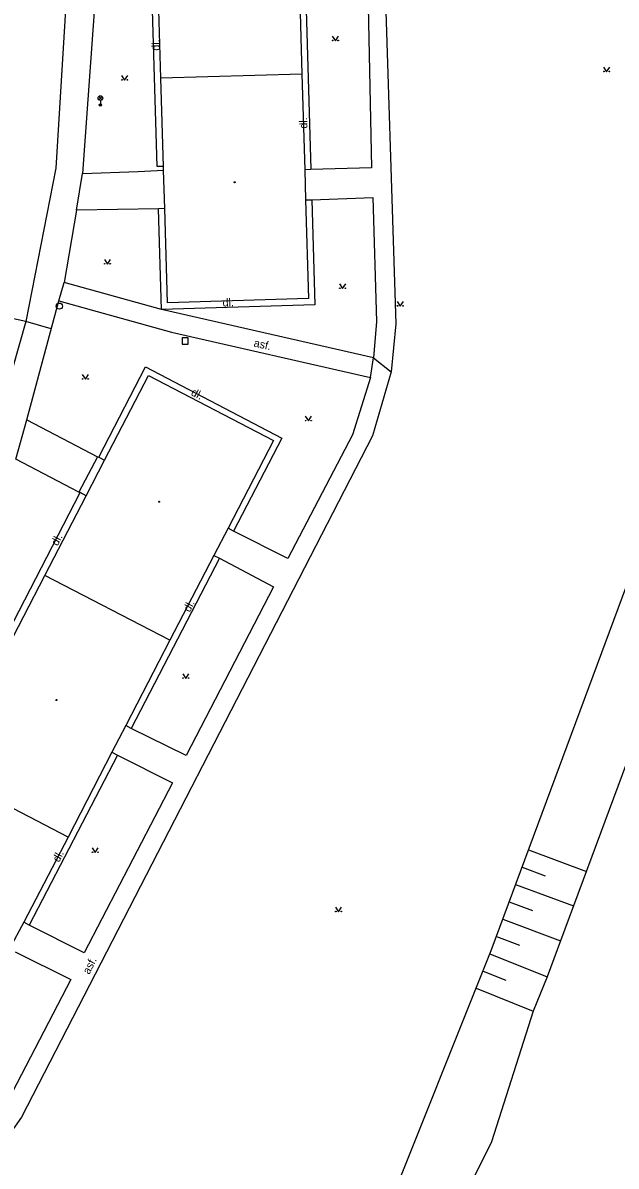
# Model space of a CAD drawing. Extents: x -602419 to -601554, y -1162937 to -1162362.
# Drawn here: x -601746.3 to -601698.2, y -1162548.7 to -1162455.9 of the extents above; entities that cross this region are included whole.
import ezdxf

# ---------------------------------------------------------------- set-up
doc = ezdxf.new("R2010")
doc.units = 0
doc.layers.add('Podklad', color=7, linetype='Continuous')

msp = doc.modelspace()

# ---------------------------------------------------------------- linework, layer by layer
at = {"layer": 'Podklad'}
for p, q in [((-601740.1625, -1162462.13), (-601739.8975, -1162461.865)), ((-601740.1625, -1162461.865), (-601739.8975, -1162462.13)), ((-601740.03, -1162462.185), (-601740.03, -1162462.56))]:
    msp.add_line(p, q, dxfattribs=at)
for points in [[(-601718.62, -1162386.7199), (-601719.1599, -1162386.65), (-601718.15, -1162413.82), (-601705.36, -1162413.11), (-601705.25, -1162448.94), (-601717.05, -1162449.02), (-601716.04, -1162480.32), (-601716.4099, -1162484.2199), (-601717.94, -1162489.4099), (-601746.45, -1162544.74), (-601749.56, -1162549.13)], [(-601734.59, -1162580.77), (-601717.04, -1162553.06), (-601708.29, -1162531.19), (-601693.48, -1162491.34), (-601681.9183, -1162447.6661), (-601678.2, -1162433.62)], [(-601742.71, -1162452.15), (-601743.65, -1162467.7)], [(-601723.89, -1162452.06), (-601723.6599, -1162460.06)], [(-601723.39, -1162452.04), (-601722.94, -1162467.8)], [(-601718.35, -1162451.9), (-601718.01, -1162467.6599)], [(-601735.84, -1162453.01), (-601740.4, -1162453.07), (-601741.48, -1162468.11), (-601736.96, -1162467.96), (-601734.9, -1162467.85)], [(-601735.4099, -1162467.56), (-601735.84, -1162453.01)], [(-601735.12, -1162460.39), (-601735.33, -1162452.99)], [(-601721.2, -1162456.975), (-601720.95, -1162457.35), (-601720.7, -1162456.975)], [(-601699.17, -1162459.485), (-601698.92, -1162459.86), (-601698.67, -1162459.485)], [(-601738.31, -1162460.165), (-601738.06, -1162460.54), (-601737.81, -1162460.165)], [(-601723.6599, -1162460.06), (-601735.12, -1162460.39)], [(-601734.9099, -1162467.55), (-601735.12, -1162460.39)], [(-601723.6599, -1162460.06), (-601723.44, -1162467.81)], [(-601743.65, -1162467.7), (-601746.09, -1162480.13)], [(-601741.98, -1162471.09), (-601741.48, -1162468.11)], [(-601734.9099, -1162467.55), (-601735.4099, -1162467.56)], [(-601734.9, -1162467.85), (-601734.9099, -1162467.55)], [(-601734.81, -1162470.9699), (-601734.9, -1162467.85)], [(-601722.94, -1162467.8), (-601723.44, -1162467.81)], [(-601723.44, -1162467.81), (-601723.37, -1162470.27)], [(-601718.01, -1162467.6599), (-601722.94, -1162467.8)], [(-601722.87, -1162470.25), (-601722.62, -1162478.77), (-601735.08, -1162479.1599)], [(-601723.37, -1162470.27), (-601722.87, -1162470.25)], [(-601723.37, -1162470.27), (-601723.14, -1162478.28)], [(-601722.87, -1162470.25), (-601717.9, -1162470.08)], [(-601717.9, -1162470.08), (-601717.61, -1162480.13)], [(-601741.98, -1162471.09), (-601742.96, -1162476.9699)], [(-601735.31, -1162470.99), (-601741.98, -1162471.09)], [(-601734.81, -1162470.9699), (-601735.31, -1162470.99)], [(-601735.08, -1162479.1599), (-601735.31, -1162470.99)], [(-601734.59, -1162478.61), (-601734.81, -1162470.9699)], [(-601685.6599, -1162472.53), (-601687.24, -1162487.32), (-601688.9699, -1162493.56), (-601702.6599, -1162530.4099), (-601703.76, -1162533.33), (-601704.88, -1162536.12), (-601708.28, -1162546.74)], [(-601739.71, -1162475.0949), (-601739.46, -1162475.4699), (-601739.21, -1162475.0949)], [(-601743.4099, -1162478.46), (-601742.96, -1162476.9699)], [(-601735.08, -1162479.1599), (-601742.96, -1162476.9699)], [(-601720.61, -1162477.085), (-601720.36, -1162477.46), (-601720.11, -1162477.085)], [(-601723.14, -1162478.28), (-601734.59, -1162478.61)], [(-601746.09, -1162480.13), (-601750.71, -1162479.13)], [(-601746.01, -1162488.13), (-601743.4099, -1162478.46), (-601734.25, -1162481), (-601718.11, -1162484.67), (-601719.57, -1162489.33), (-601724.81, -1162499.38), (-601729.21, -1162497.15)], [(-601717.85, -1162483.08), (-601735.08, -1162479.1599)], [(-601715.93, -1162478.515), (-601715.68, -1162478.89), (-601715.43, -1162478.515)], [(-601746.09, -1162480.13), (-601748.9, -1162489.95)], [(-601744.0177, -1162480.7205), (-601746.09, -1162480.13)], [(-601717.61, -1162480.13), (-601717.85, -1162483.08)], [(-601740.17, -1162491.15), (-601736.36, -1162483.82), (-601725.3, -1162489.62), (-601729.21, -1162497.15)], [(-601718.11, -1162484.67), (-601717.85, -1162483.08), (-601716.4099, -1162484.2199)], [(-601741.5, -1162484.445), (-601741.25, -1162484.82), (-601741, -1162484.445)], [(-601739.69, -1162491.4), (-601736.13, -1162484.53)], [(-601736.13, -1162484.53), (-601725.9699, -1162489.79)], [(-601746.9099, -1162491.32), (-601746.01, -1162488.13)], [(-601746.01, -1162488.13), (-601740.26, -1162491.11)], [(-601723.39, -1162487.835), (-601723.14, -1162488.21), (-601722.89, -1162487.835)], [(-601725.9699, -1162489.79), (-601729.6599, -1162496.92)], [(-601741.77, -1162493.99), (-601746.9099, -1162491.32)], [(-601740.26, -1162491.11), (-601741.77, -1162493.99)], [(-601740.26, -1162491.11), (-601740.17, -1162491.15)], [(-601740.17, -1162491.15), (-601739.69, -1162491.4)], [(-601741.19, -1162494.29), (-601739.69, -1162491.4)], [(-601748.44, -1162507.1), (-601741.68, -1162494.03)], [(-601741.68, -1162494.03), (-601741.77, -1162493.99)], [(-601741.19, -1162494.29), (-601741.68, -1162494.03)], [(-601744.53, -1162500.75), (-601741.19, -1162494.29)], [(-601729.6599, -1162496.92), (-601730.81, -1162499.13)], [(-601729.21, -1162497.15), (-601729.6599, -1162496.92)], [(-601730.36, -1162499.36), (-601725.9699, -1162501.68), (-601733.06, -1162515.37), (-601737.53, -1162513.17)], [(-601730.36, -1162499.36), (-601737.53, -1162513.17)], [(-601730.81, -1162499.13), (-601734.38, -1162506.01)], [(-601730.81, -1162499.13), (-601730.36, -1162499.36)], [(-601747.95, -1162507.35), (-601744.53, -1162500.75)], [(-601734.38, -1162506.01), (-601744.53, -1162500.75)], [(-601734.38, -1162506.01), (-601737.9699, -1162512.94)], [(-601733.34, -1162508.735), (-601733.09, -1162509.11), (-601732.84, -1162508.735)], [(-601737.9699, -1162512.94), (-601739.1, -1162515.11)], [(-601737.53, -1162513.17), (-601737.9699, -1162512.94)], [(-601738.65, -1162515.34), (-601734.17, -1162517.58), (-601741.36, -1162531.38), (-601745.81, -1162529.14)], [(-601738.65, -1162515.34), (-601745.81, -1162529.14)], [(-601739.1, -1162515.11), (-601742.6599, -1162521.99)], [(-601739.1, -1162515.11), (-601738.65, -1162515.34)], [(-601742.6599, -1162521.99), (-601752.81, -1162516.73)], [(-601742.6599, -1162521.99), (-601746.26, -1162528.9)], [(-601740.7, -1162522.875), (-601740.45, -1162523.25), (-601740.2, -1162522.875)], [(-601746.94, -1162531.3), (-601742.42, -1162533.57), (-601747.9, -1162544.08), (-601750.49, -1162547.64), (-601750.6322, -1162547.5095), (-601762.35, -1162536.76), (-601769.69, -1162529.9), (-601763.99, -1162523.05)], [(-601705.26, -1162523.04), (-601700.57, -1162524.78)], [(-601705.78, -1162524.45), (-601703.9099, -1162525.14)], [(-601706.31, -1162525.85), (-601701.62, -1162527.59)], [(-601706.83, -1162527.26), (-601704.95, -1162527.95)], [(-601720.94, -1162527.685), (-601720.69, -1162528.06), (-601720.44, -1162527.685)], [(-601746.26, -1162528.9), (-601747.4, -1162531.07)], [(-601745.81, -1162529.14), (-601746.26, -1162528.9)], [(-601707.35, -1162528.6599), (-601702.6599, -1162530.4099)], [(-601707.87, -1162530.07), (-601706, -1162530.77)], [(-601708.4, -1162531.4699), (-601703.76, -1162533.33)], [(-601708.96, -1162532.87), (-601707.1, -1162533.61)], [(-601709.52, -1162534.26), (-601704.88, -1162536.12)], [(-601708.28, -1162546.74), (-601722.84, -1162575.9)]]:
    msp.add_lwpolyline(points, dxfattribs=at)
msp.add_lwpolyline([(-601733.4, -1162481.9699), (-601732.9, -1162481.9699), (-601732.9, -1162481.4699), (-601733.4, -1162481.4699)], close=True, dxfattribs=at)
for centre, radius in [((-601721.1751, -1162457.3249), 0.025), ((-601720.7254, -1162457.3249), 0.025), ((-601699.1451, -1162459.8349), 0.025), ((-601698.6954, -1162459.8349), 0.025), ((-601738.2851, -1162460.5149), 0.025), ((-601737.8354, -1162460.5149), 0.025), ((-601740.03, -1162461.9975), 0.1875), ((-601740.03, -1162462.56), 0.1), ((-601740.03, -1162462.56), 0.0723), ((-601740.03, -1162462.56), 0.0438), ((-601729.13, -1162468.83), 0.045), ((-601729.13, -1162468.83), 0.0199), ((-601739.6851, -1162475.4448), 0.025), ((-601739.2354, -1162475.4448), 0.025), ((-601720.5851, -1162477.4349), 0.025), ((-601720.1354, -1162477.4349), 0.025), ((-601743.36, -1162478.89), 0.25), ((-601715.9051, -1162478.8649), 0.025), ((-601715.4554, -1162478.8649), 0.025), ((-601741.4751, -1162484.7949), 0.025), ((-601741.0254, -1162484.7949), 0.025), ((-601723.3651, -1162488.1849), 0.025), ((-601722.9154, -1162488.1849), 0.025), ((-601735.25, -1162494.77), 0.045), ((-601735.25, -1162494.77), 0.0199), ((-601733.3151, -1162509.0849), 0.025), ((-601732.8654, -1162509.0849), 0.025), ((-601743.6, -1162510.87), 0.045), ((-601743.6, -1162510.87), 0.0199), ((-601740.6751, -1162523.2249), 0.025), ((-601740.2254, -1162523.2249), 0.025), ((-601720.9151, -1162528.0349), 0.025), ((-601720.4654, -1162528.0349), 0.025)]:
    msp.add_circle(centre, radius, dxfattribs=at)

# ---------------------------------------------------------------- texts
for s, rotation, p in [('dl.', 91.65, (-601735.2, -1162458.14)), ('dl.', 91.65, (-601723.2199, -1162464.4699)), ('dl.', 1.65, (-601730.1, -1162478.92)), ('asf.', 347.19, (-601727.62, -1162482.1599)), ('dl.', 332.63, (-601732.73, -1162486.09)), ('dl.', 62.59, (-601743.5, -1162498.4)), ('dl.', 62.59, (-601732.77, -1162503.78)), ('dl.', 62.59, (-601743.39, -1162524.09)), ('asf.', 62.74, (-601740.94, -1162533.19))]:
    msp.add_text(s, height=0.65, rotation=rotation, dxfattribs=at).set_placement(p)

doc.saveas('drawing.dxf')
